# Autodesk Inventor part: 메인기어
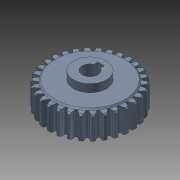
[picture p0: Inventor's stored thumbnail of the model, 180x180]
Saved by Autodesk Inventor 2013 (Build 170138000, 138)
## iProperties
Created: 2011-08
Part Number: 메인기어
Document SubType Name: Modeling
Designer: KYOUNG IL JANG
Density: 1 g/cm^3
Material: 일반
Mass: 53.8876 g
Surface Area: 135.188 cm^2
Volume: 53.8876 cm^3
Description: 잇수:30 / PCD:60
Author: mm
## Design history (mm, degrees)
sketch "스케치1"
  geometry: C1 r 27.5 at (0, 0); A1 r 27.5 centre (0, 0) between (2.757, 27.361) and (-2.757, 27.361); A2 r 32 centre (0, 0) between (0.737, 31.992) and (-0.737, 31.992); A3 r 1.004 centre (-2.903, 28.355) between (-2.757, 27.361) and (-1.899, 28.332); A4 r 7.498 centre (5.568, 27.656) between (-1.648, 29.691) and (-1.899, 28.332); A5 r 12.465 centre (10.34, 26.276) between (-0.737, 31.992) and (-1.648, 29.691); A6 r 1.004 centre (2.903, 28.355) between (1.899, 28.332) and (2.757, 27.361); A7 r 7.498 centre (-5.568, 27.656) between (1.899, 28.332) and (1.648, 29.691); A8 r 12.465 centre (-10.34, 26.276) between (1.648, 29.691) and (0.737, 31.992); 1 further point
  constraints: 16 point on circle, 9 centre point, 1 coincident, 1 concentric
extrude "돌출1" new body sketch "스케치1" stored distance "d0" = 20; taper "d1" = 0 deg
extrude "돌출2" join sketch "스케치1" stored distance "d2" = 18; taper "d3" = 0 deg
chamfer "모따기1" distance "d4" = 1; stored, may be unused: second distance "d5" = 2, angle "d6" = 45 deg
sketch "스케치2"
  geometry: 1 further point
hole "구멍1" sketch "스케치2" at (0, 0) diameter "d10" = 12; stored, may be unused: countersink angle "d14" = 90 deg, drill point angle "d16" = 118 deg; dims "d11" = 6, "d12" = 4, "d13" = 2, "d15" = 8
sketch "스케치3"
  geometry: L1 (-2.5, 5.454)-(-2.5, 8.5); L2 (-2.5, 8.5)-(2.5, 8.5); L3 (2.5, 8.5)-(2.5, 5.454); C1 r 6 at (0, 0); A1 r 6 centre (0, 0) between (-2.5, 5.454) and (2.5, 5.454) reference; 1 further point
  constraints: 6 end point, 2 point on circle, 2 vertical, 1 centre point, 1 coincident, 1 horizontal, 1 parallel
  dimensions: "d17" = 2.5 distance edge to line of A1 L2; "d18" = 5 distance of L1.end L2.end; "d27" = 12 diameter of C1
extrude "돌출3" cut sketch "스케치3" stored distance "d19" = 10; taper "d20" = 0 deg
chamfer "모따기2" distance "d21" = 1; stored, may be unused: second distance "d22" = 2, angle "d23" = 45 deg
chamfer "모따기3" distance "d24" = 1; stored, may be unused: second distance "d25" = 2, angle "d26" = 45 deg
sketch "스케치4"
  geometry: L1 (2.5, 8.5)-(2.5, 5.454) reference; L2 (-2.5, 8.5)-(2.5, 8.5) reference; L3 (-2.5, 5.454)-(-2.5, 8.5) reference; C1 r 11 at (0, 0); A1 r 6 centre (0, 0) between (-2.5, 5.454) and (2.5, 5.454) reference; 1 further point
  constraints: 1 centre point, 1 coincident
  dimensions: "d28" = 22 diameter of C1
extrude "돌출4" join sketch "스케치4" distance "d30" = 6; taper "d31" = 0 deg
chamfer "모따기4" distance "d40" = 1; stored, may be unused: second distance "d41" = 2, angle "d42" = 45 deg
node "작업 평면1"
sketch "스케치5"
  geometry: L1 (11, 6)-(-11, 6) reference; 2 further points
  constraints: 1 vertical alignment
  dimensions: "d32" = 3 distance from line of point (0, 3) L1
hole "구멍2" sketch "스케치5" at (0, 3) diameter "d33" = 2.459; stored, may be unused: countersink angle "d37" = 90 deg, drill point angle "d39" = 118 deg; dims "d34" = 6, "d35" = 4, "d36" = 2, "d38" = 8
node "솔리드1"
pattern_circular "원형 패턴1" dims angle "d8" = 360 deg
